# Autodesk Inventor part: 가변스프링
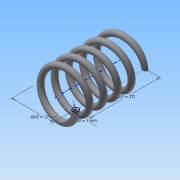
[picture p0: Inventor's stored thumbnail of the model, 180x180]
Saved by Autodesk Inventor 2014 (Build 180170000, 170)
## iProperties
Created: 2015-09
Part Number: 가변스프링
Material: Generic
Document SubType Name: Modeling
Designer: study
Density: 1 g/cm^3
Appearance: Default
Author: study
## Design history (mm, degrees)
sketch "스케치1"
  geometry: L1 (0, 0)-(11, 0); L2 (11, 0)-(11, 37); L3 (11, 37)-(0, 37); L4 (0, 37)-(0, 0); C1 r 1.5 at (11, 0)
  constraints: 8 end point, 2 parallel, 1 centre point, 1 coincident, 1 horizontal, 1 perpendicular
  dimensions: "d0" = 3 diameter of C1; "d2" = 22 diameter of L2 L4; "d3" = 37 distance of L1.end L2.end (derived)
feature "코일1" sketch "스케치1" pitch "d4" = 10; turns "d6" = 5; dims "d5" = 37 (= d3), "d7" = 0, angle "d8" = 90 deg, angle "d9" = 90 deg, "d10" = 0, "d11" = 0
node "작업 평면1"
sketch "스케치2"
  geometry: L1 (-12.5, 0)-(-9.5, 0) reference; 1 further point
  constraints: 1 horizontal alignment
extrude "돌출1" cut sketch "스케치2" stored distance "d13" = 10; taper "d14" = 0 deg
node "작업 평면2"
sketch "스케치3"
  geometry: L1 (-9.5, 0)-(-12.5, 0) reference; 1 further point
  constraints: 1 horizontal alignment
extrude "돌출2" cut sketch "스케치3" stored distance "d16" = 10; taper "d17" = 0 deg
node "솔리드1"
node "절단 모서리 투영1"
node "절단 모서리 투영2"
other parameters: "d12" = 0, "d15" = 37 (= d3)
